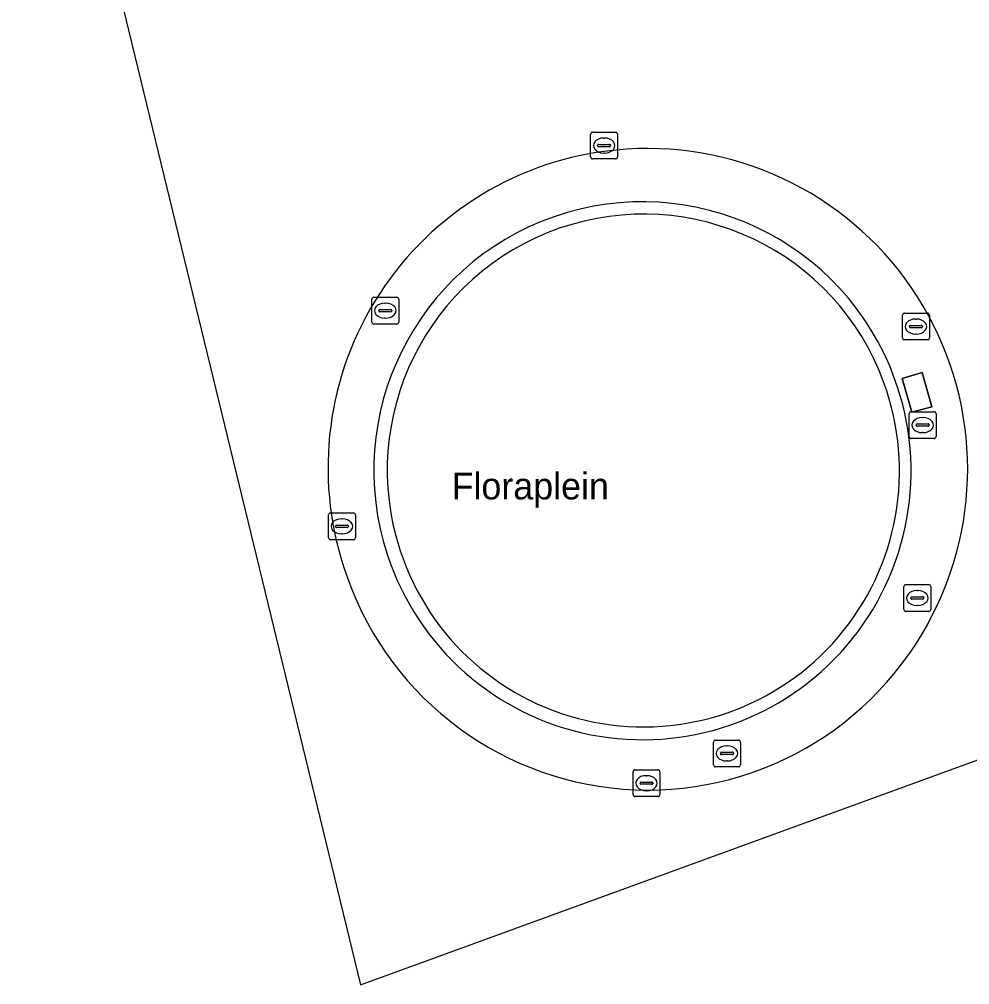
# Model space of a CAD drawing. Extents: x 162542 to 163147, y 380779 to 381521.
# Drawn here: x 162648.54 to 162684.01, y 380779.12 to 380815.13 of the extents above; entities that cross this region are included whole.
import ezdxf

# ---------------------------------------------------------------- set-up
doc = ezdxf.new("R2010")
doc.units = 0
for name, color, linetype in [('IMGEO_Brandkraan', 7, 'Continuous'), ('IMGEO_Kolk', 7, 'Continuous'), ('IMGEO_Meer_plas_ven_vijver', 7, 'Continuous'), ('IMGEO_Muur', 7, 'Continuous'), ('IMGEO_Openbare_ruimte_label', 7, 'Continuous'), ('IMGEO_Rioolput', 7, 'Continuous'), ('IMGEO_Terreindeel_open', 7, 'Continuous'), ('IMGEO_Verkeerseiland_groen', 7, 'Continuous')]:
    doc.layers.add(name, color=color, linetype=linetype)

msp = doc.modelspace()

# ---------------------------------------------------------------- linework, layer by layer
at = {"layer": 'IMGEO_Brandkraan'}
for p, q in [((162681.751, 380799.567), (162681.751, 380800.419)), ((162681.826, 380800.493), (162682.678, 380800.493)), ((162682.752, 380800.419), (162682.752, 380799.567)), ((162682.01, 380799.987), (162682.01, 380799.999)), ((162682.053, 380800.036), (162682.451, 380800.036)), ((162682.239, 380800.273), (162682.264, 380800.273)), ((162682.494, 380799.999), (162682.494, 380799.987)), ((162682.448, 380799.95), (162682.05, 380799.95)), ((162682.262, 380799.713), (162682.237, 380799.713)), ((162682.678, 380799.493), (162681.826, 380799.493))]:
    msp.add_line(p, q, dxfattribs=at)
for points in [[(162681.751, 380799.567), (162681.751, 380800.419)], [(162681.826, 380800.493), (162682.678, 380800.493)], [(162682.752, 380800.419), (162682.752, 380799.567)], [(162682.678, 380799.493), (162681.826, 380799.493)]]:
    msp.add_lwpolyline(points, dxfattribs=at)
for centre, radius, start, end in [((162681.828, 380800.417), 0.0765, 91.552, 178.448), ((162681.828, 380800.417), 0.0765, 91.552, 178.448), ((162682.676, 380800.417), 0.0765, 1.552, 88.448), ((162682.676, 380800.417), 0.0765, 1.552, 88.448), ((162682.05, 380799.996), 0.0403, 85.8775, 175.7526), ((162682.047, 380799.986), 0.0366, 178.938, 274.7102), ((162682.451, 380799.993), 0.043, 264.8664, 352.4533), ((162682.455, 380799.998), 0.0386, 1.7309, 96.639), ((162681.828, 380799.569), 0.0765, 181.552, 268.448), ((162681.828, 380799.569), 0.0765, 181.552, 268.448), ((162682.676, 380799.569), 0.0765, 271.552, 358.448), ((162682.676, 380799.569), 0.0765, 271.552, 358.448)]:
    msp.add_arc(centre, radius, start, end, dxfattribs=at)
for centre, major_axis, ratio, start_param, end_param in [((162682.238, 380799.993), (-0.387, 0.002), 0.722429, 4.712389, 7.853982), ((162682.263, 380799.993), (-0.39, 0.002), 0.717154, 1.570796, 4.712389)]:
    msp.add_ellipse(centre, major_axis=major_axis, ratio=ratio, start_param=start_param, end_param=end_param, dxfattribs=at)
at = {"layer": 'IMGEO_Kolk'}
for p, q in [((162681.499, 380803.245), (162681.499, 380804.097)), ((162681.574, 380804.171), (162682.426, 380804.171)), ((162681.987, 380803.951), (162682.012, 380803.951)), ((162682.5, 380804.097), (162682.5, 380803.245)), ((162681.758, 380803.665), (162681.758, 380803.677)), ((162682.196, 380803.628), (162681.798, 380803.628)), ((162681.801, 380803.714), (162682.199, 380803.714)), ((162682.242, 380803.677), (162682.242, 380803.665)), ((162682.01, 380803.391), (162681.985, 380803.391)), ((162682.426, 380803.171), (162681.574, 380803.171)), ((162660.082, 380795.792), (162660.082, 380796.644)), ((162660.157, 380796.718), (162661.009, 380796.718)), ((162660.57, 380796.498), (162660.595, 380796.498)), ((162661.083, 380796.644), (162661.083, 380795.792)), ((162660.341, 380796.212), (162660.341, 380796.224)), ((162660.779, 380796.175), (162660.381, 380796.175)), ((162660.384, 380796.261), (162660.782, 380796.261)), ((162660.825, 380796.224), (162660.825, 380796.212)), ((162661.009, 380795.718), (162660.157, 380795.718)), ((162660.593, 380795.938), (162660.568, 380795.938)), ((162674.449, 380787.318), (162674.449, 380788.17)), ((162674.524, 380788.244), (162675.376, 380788.244)), ((162675.45, 380788.17), (162675.45, 380787.318)), ((162674.708, 380787.738), (162674.708, 380787.75)), ((162674.751, 380787.787), (162675.149, 380787.787)), ((162674.937, 380788.024), (162674.962, 380788.024)), ((162675.192, 380787.75), (162675.192, 380787.738)), ((162675.146, 380787.701), (162674.748, 380787.701)), ((162674.96, 380787.464), (162674.935, 380787.464)), ((162671.446, 380786.209), (162671.446, 380787.061)), ((162671.521, 380787.135), (162672.373, 380787.135)), ((162672.447, 380787.061), (162672.447, 380786.209)), ((162675.376, 380787.244), (162674.524, 380787.244)), ((162671.748, 380786.678), (162672.146, 380786.678)), ((162671.934, 380786.915), (162671.959, 380786.915)), ((162671.705, 380786.629), (162671.705, 380786.641)), ((162672.143, 380786.592), (162671.745, 380786.592)), ((162671.957, 380786.355), (162671.932, 380786.355)), ((162672.189, 380786.641), (162672.189, 380786.629)), ((162672.373, 380786.135), (162671.521, 380786.135))]:
    msp.add_line(p, q, dxfattribs=at)
for points in [[(162681.499, 380803.245), (162681.499, 380804.097)], [(162681.574, 380804.171), (162682.426, 380804.171)], [(162682.5, 380804.097), (162682.5, 380803.245)], [(162682.426, 380803.171), (162681.574, 380803.171)], [(162660.082, 380795.792), (162660.082, 380796.644)], [(162660.157, 380796.718), (162661.009, 380796.718)], [(162661.083, 380796.644), (162661.083, 380795.792)], [(162661.009, 380795.718), (162660.157, 380795.718)], [(162674.449, 380787.318), (162674.449, 380788.17)], [(162674.524, 380788.244), (162675.376, 380788.244)], [(162675.45, 380788.17), (162675.45, 380787.318)], [(162671.446, 380786.209), (162671.446, 380787.061)], [(162671.521, 380787.135), (162672.373, 380787.135)], [(162672.447, 380787.061), (162672.447, 380786.209)], [(162675.376, 380787.244), (162674.524, 380787.244)], [(162672.373, 380786.135), (162671.521, 380786.135)]]:
    msp.add_lwpolyline(points, dxfattribs=at)
for centre, radius, start, end in [((162681.576, 380804.095), 0.0765, 91.552, 178.448), ((162681.576, 380804.095), 0.0765, 91.552, 178.448), ((162682.424, 380804.095), 0.0765, 1.552, 88.448), ((162682.424, 380804.095), 0.0765, 1.552, 88.448), ((162681.798, 380803.674), 0.0403, 85.8775, 175.7526), ((162681.795, 380803.664), 0.0366, 178.938, 274.7102), ((162682.199, 380803.671), 0.043, 264.8664, 352.4533), ((162682.203, 380803.676), 0.0386, 1.7309, 96.639), ((162681.576, 380803.247), 0.0765, 181.552, 268.448), ((162681.576, 380803.247), 0.0765, 181.552, 268.448), ((162682.424, 380803.247), 0.0765, 271.552, 358.448), ((162682.424, 380803.247), 0.0765, 271.552, 358.448), ((162660.159, 380796.642), 0.0765, 91.552, 178.448), ((162660.159, 380796.642), 0.0765, 91.552, 178.448), ((162661.007, 380796.642), 0.0765, 1.552, 88.448), ((162661.007, 380796.642), 0.0765, 1.552, 88.448), ((162660.381, 380796.221), 0.0403, 85.8775, 175.7526), ((162660.378, 380796.211), 0.0366, 178.938, 274.7102), ((162660.782, 380796.218), 0.043, 264.8664, 352.4533), ((162660.786, 380796.223), 0.0386, 1.7309, 96.639), ((162660.159, 380795.794), 0.0765, 181.552, 268.448), ((162660.159, 380795.794), 0.0765, 181.552, 268.448), ((162661.007, 380795.794), 0.0765, 271.552, 358.448), ((162661.007, 380795.794), 0.0765, 271.552, 358.448), ((162674.526, 380788.168), 0.0765, 91.552, 178.448), ((162674.526, 380788.168), 0.0765, 91.552, 178.448), ((162675.374, 380788.168), 0.0765, 1.552, 88.448), ((162675.374, 380788.168), 0.0765, 1.552, 88.448), ((162674.748, 380787.747), 0.0403, 85.8775, 175.7526), ((162674.745, 380787.737), 0.0366, 178.938, 274.7102), ((162675.149, 380787.744), 0.043, 264.8664, 352.4533), ((162675.153, 380787.749), 0.0386, 1.7309, 96.639), ((162671.523, 380787.059), 0.0765, 91.552, 178.448), ((162671.523, 380787.059), 0.0765, 91.552, 178.448), ((162672.371, 380787.059), 0.0765, 1.552, 88.448), ((162672.371, 380787.059), 0.0765, 1.552, 88.448), ((162674.526, 380787.32), 0.0765, 181.552, 268.448), ((162674.526, 380787.32), 0.0765, 181.552, 268.448), ((162675.374, 380787.32), 0.0765, 271.552, 358.448), ((162675.374, 380787.32), 0.0765, 271.552, 358.448), ((162671.745, 380786.638), 0.0403, 85.8775, 175.7526), ((162672.15, 380786.64), 0.0386, 1.7309, 96.639), ((162671.742, 380786.628), 0.0366, 178.938, 274.7102), ((162672.146, 380786.635), 0.043, 264.8664, 352.4533), ((162671.523, 380786.211), 0.0765, 181.552, 268.448), ((162671.523, 380786.211), 0.0765, 181.552, 268.448), ((162672.371, 380786.211), 0.0765, 271.552, 358.448), ((162672.371, 380786.211), 0.0765, 271.552, 358.448)]:
    msp.add_arc(centre, radius, start, end, dxfattribs=at)
for centre, major_axis, ratio, start_param, end_param in [((162681.986, 380803.671), (-0.387, 0.002), 0.722429, 4.712389, 7.853982), ((162682.011, 380803.671), (-0.39, 0.002), 0.717154, 1.570796, 4.712389), ((162660.569, 380796.218), (-0.387, 0.002), 0.722429, 4.712389, 7.853982), ((162660.594, 380796.218), (-0.39, 0.002), 0.717154, 1.570796, 4.712389), ((162674.936, 380787.744), (-0.387, 0.002), 0.722429, 4.712389, 7.853982), ((162674.961, 380787.744), (-0.39, 0.002), 0.717154, 1.570796, 4.712389), ((162671.933, 380786.635), (-0.387, 0.002), 0.722429, 4.712389, 7.853982), ((162671.958, 380786.635), (-0.39, 0.002), 0.717154, 1.570796, 4.712389)]:
    msp.add_ellipse(centre, major_axis=major_axis, ratio=ratio, start_param=start_param, end_param=end_param, dxfattribs=at)
at = {"layer": 'IMGEO_Meer_plas_ven_vijver'}
for centre, start, end in [((162671.827, 380798.309), 19.9802, 198.3103), ((162671.834, 380798.289), 198.1785, 20.112)]:
    msp.add_arc(centre, 9.554, start, end, dxfattribs=at)
at = {"layer": 'IMGEO_Muur'}
for centre, radius, start, end in [((162671.79, 380798.304), 10.018, 19.9661, 198.3889), ((162671.827, 380798.309), 9.554, 19.9802, 198.3103), ((162671.801, 380798.273), 10.018, 198.2018, 20.1531), ((162671.834, 380798.289), 9.554, 198.1785, 20.112)]:
    msp.add_arc(centre, radius, start, end, dxfattribs=at)
at = {"layer": 'IMGEO_Rioolput'}
for p, q in [((162669.863, 380809.997), (162669.863, 380810.849)), ((162669.938, 380810.923), (162670.79, 380810.923)), ((162670.864, 380810.849), (162670.864, 380809.997)), ((162670.122, 380810.417), (162670.122, 380810.429)), ((162670.165, 380810.466), (162670.563, 380810.466)), ((162670.351, 380810.703), (162670.376, 380810.703)), ((162670.606, 380810.429), (162670.606, 380810.417)), ((162670.56, 380810.38), (162670.162, 380810.38)), ((162670.374, 380810.143), (162670.349, 380810.143)), ((162670.79, 380809.923), (162669.938, 380809.923)), ((162661.7, 380803.838), (162661.7, 380804.69)), ((162661.775, 380804.764), (162662.627, 380804.764)), ((162662.701, 380804.69), (162662.701, 380803.838)), ((162662.002, 380804.307), (162662.4, 380804.307)), ((162662.188, 380804.544), (162662.213, 380804.544)), ((162661.959, 380804.258), (162661.959, 380804.27)), ((162662.397, 380804.221), (162661.999, 380804.221)), ((162662.211, 380803.984), (162662.186, 380803.984)), ((162662.443, 380804.27), (162662.443, 380804.258)), ((162662.627, 380803.764), (162661.775, 380803.764)), ((162681.551, 380793.118), (162681.551, 380793.97)), ((162681.626, 380794.044), (162682.478, 380794.044)), ((162682.552, 380793.97), (162682.552, 380793.118)), ((162681.81, 380793.538), (162681.81, 380793.55)), ((162682.248, 380793.501), (162681.85, 380793.501)), ((162681.853, 380793.587), (162682.251, 380793.587)), ((162682.039, 380793.824), (162682.064, 380793.824)), ((162682.294, 380793.55), (162682.294, 380793.538)), ((162682.062, 380793.264), (162682.037, 380793.264)), ((162682.478, 380793.044), (162681.626, 380793.044))]:
    msp.add_line(p, q, dxfattribs=at)
for points in [[(162669.863, 380809.997), (162669.863, 380810.849)], [(162669.938, 380810.923), (162670.79, 380810.923)], [(162670.864, 380810.849), (162670.864, 380809.997)], [(162670.79, 380809.923), (162669.938, 380809.923)], [(162661.7, 380803.838), (162661.7, 380804.69)], [(162661.775, 380804.764), (162662.627, 380804.764)], [(162662.701, 380804.69), (162662.701, 380803.838)], [(162662.627, 380803.764), (162661.775, 380803.764)], [(162681.551, 380793.118), (162681.551, 380793.97)], [(162681.626, 380794.044), (162682.478, 380794.044)], [(162682.552, 380793.97), (162682.552, 380793.118)], [(162682.478, 380793.044), (162681.626, 380793.044)]]:
    msp.add_lwpolyline(points, dxfattribs=at)
for centre, radius, start, end in [((162669.94, 380810.847), 0.0765, 91.552, 178.448), ((162669.94, 380810.847), 0.0765, 91.552, 178.448), ((162670.788, 380810.847), 0.0765, 1.552, 88.448), ((162670.788, 380810.847), 0.0765, 1.552, 88.448), ((162670.162, 380810.426), 0.0403, 85.8775, 175.7526), ((162670.567, 380810.428), 0.0386, 1.7309, 96.639), ((162670.159, 380810.416), 0.0366, 178.938, 274.7102), ((162670.563, 380810.423), 0.043, 264.8664, 352.4533), ((162669.94, 380809.999), 0.0765, 181.552, 268.448), ((162669.94, 380809.999), 0.0765, 181.552, 268.448), ((162670.788, 380809.999), 0.0765, 271.552, 358.448), ((162670.788, 380809.999), 0.0765, 271.552, 358.448), ((162661.777, 380804.688), 0.0765, 91.552, 178.448), ((162661.777, 380804.688), 0.0765, 91.552, 178.448), ((162662.625, 380804.688), 0.0765, 1.552, 88.448), ((162662.625, 380804.688), 0.0765, 1.552, 88.448), ((162661.999, 380804.267), 0.0403, 85.8775, 175.7526), ((162662.404, 380804.269), 0.0386, 1.7309, 96.639), ((162661.996, 380804.257), 0.0366, 178.938, 274.7102), ((162662.4, 380804.264), 0.043, 264.8664, 352.4533), ((162661.777, 380803.84), 0.0765, 181.552, 268.448), ((162661.777, 380803.84), 0.0765, 181.552, 268.448), ((162662.625, 380803.84), 0.0765, 271.552, 358.448), ((162662.625, 380803.84), 0.0765, 271.552, 358.448), ((162681.628, 380793.968), 0.0765, 91.552, 178.448), ((162681.628, 380793.968), 0.0765, 91.552, 178.448), ((162682.476, 380793.968), 0.0765, 1.552, 88.448), ((162682.476, 380793.968), 0.0765, 1.552, 88.448), ((162681.85, 380793.547), 0.0403, 85.8775, 175.7526), ((162681.847, 380793.537), 0.0366, 178.938, 274.7102), ((162682.251, 380793.544), 0.043, 264.8664, 352.4533), ((162682.255, 380793.549), 0.0386, 1.7309, 96.639), ((162681.628, 380793.12), 0.0765, 181.552, 268.448), ((162681.628, 380793.12), 0.0765, 181.552, 268.448), ((162682.476, 380793.12), 0.0765, 271.552, 358.448), ((162682.476, 380793.12), 0.0765, 271.552, 358.448)]:
    msp.add_arc(centre, radius, start, end, dxfattribs=at)
for centre, major_axis, ratio, start_param, end_param in [((162670.35, 380810.423), (-0.387, 0.002), 0.722429, 4.712389, 7.853982), ((162670.375, 380810.423), (-0.39, 0.002), 0.717154, 1.570796, 4.712389), ((162662.187, 380804.264), (-0.387, 0.002), 0.722429, 4.712389, 7.853982), ((162662.212, 380804.264), (-0.39, 0.002), 0.717154, 1.570796, 4.712389), ((162682.038, 380793.544), (-0.387, 0.002), 0.722429, 4.712389, 7.853982), ((162682.063, 380793.544), (-0.39, 0.002), 0.717154, 1.570796, 4.712389)]:
    msp.add_ellipse(centre, major_axis=major_axis, ratio=ratio, start_param=start_param, end_param=end_param, dxfattribs=at)
at = {"layer": 'IMGEO_Terreindeel_open'}
for points in [[(162682.592, 380800.67), (162681.846, 380800.475), (162681.484, 380801.738), (162682.236, 380801.961)], [(162682.592, 380800.67), (162682.236, 380801.961), (162681.484, 380801.738), (162681.846, 380800.475)]]:
    msp.add_lwpolyline(points, close=True, dxfattribs=at)
for centre, radius, start, end in [((162671.971, 380798.404), 11.909, 95.6003, 198.2129), ((162671.975, 380798.358), 11.955, 333.2245, 95.5984), ((162671.79, 380798.304), 10.018, 19.9661, 198.3889), ((162671.801, 380798.273), 10.018, 198.2018, 20.1531), ((162671.999, 380798.275), 11.896, 197.5799, 333.5318)]:
    msp.add_arc(centre, radius, start, end, dxfattribs=at)
at = {"layer": 'IMGEO_Verkeerseiland_groen'}
msp.add_lwpolyline([(162648.544, 380831.522), (162661.275, 380779.117), (162711, 380797.226)], dxfattribs=at)
for centre, radius, start, end in [((162671.971, 380798.404), 11.909, 95.6003, 198.2129), ((162671.975, 380798.358), 11.955, 333.2245, 95.5984), ((162671.999, 380798.275), 11.896, 197.5799, 333.5318)]:
    msp.add_arc(centre, radius, start, end, dxfattribs=at)

# ---------------------------------------------------------------- texts
at = {"layer": 'IMGEO_Openbare_ruimte_label'}
msp.add_text('Floraplein', height=1, dxfattribs=at).set_placement((162664.673, 380797.221))

doc.saveas('drawing.dxf')
